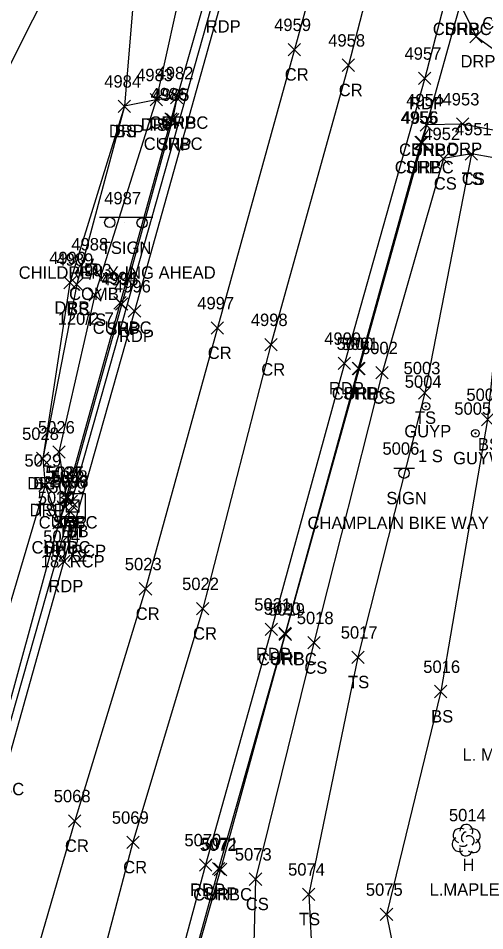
# Model space of a CAD drawing. Extents: x 1443912 to 1445411, y 621446 to 623693.
# Drawn here: x 1444769.5 to 1444844.8, y 622698.4 to 622845.6 of the extents above; entities that cross this region are included whole.
import ezdxf

# ---------------------------------------------------------------- set-up
doc = ezdxf.new("R2010")
doc.units = 0
for name, color, linetype in [('D_A', 7, 'Continuous'), ('D_C', 7, 'Continuous'), ('D_I', 7, 'Continuous'), ('D_TIC', 7, 'Continuous'), ('DCP', 7, 'Continuous'), ('DS', 7, 'Continuous'), ('L_A', 7, 'Continuous'), ('L_C', 7, 'Continuous'), ('L_I', 7, 'Continuous'), ('L_TIC', 7, 'Continuous'), ('LELB', 7, 'Continuous'), ('LTD', 7, 'Continuous'), ('P_A', 7, 'Continuous'), ('P_I', 7, 'Continuous'), ('P_TIC', 7, 'Continuous'), ('PET', 7, 'Continuous'), ('PRC', 7, 'Continuous'), ('PSP', 7, 'Continuous'), ('R_A', 7, 'Continuous'), ('R_I', 7, 'Continuous'), ('R_TIC', 7, 'Continuous'), ('RC', 7, 'Continuous'), ('RDP', 7, 'Continuous'), ('S_A', 7, 'Continuous'), ('S_C', 7, 'Continuous'), ('S_I', 7, 'Continuous'), ('SSGN', 7, 'Continuous'), ('U_A', 7, 'Continuous'), ('U_C', 7, 'Continuous'), ('U_I', 7, 'Continuous'), ('UP', 7, 'Continuous'), ('UPGW', 7, 'Continuous')]:
    doc.layers.add(name, color=color, linetype=linetype)

msp = doc.modelspace()

# ---------------------------------------------------------------- linework, layer by layer
at = {"layer": 'D_TIC'}
for points in [[(1444777.13, 622766.66), (1444779.13, 622768.66)], [(1444779.13, 622766.66), (1444777.13, 622768.66)], [(1444776.89, 622765), (1444778.89, 622767)], [(1444778.89, 622765), (1444776.89, 622767)], [(1444777.35, 622765.86), (1444779.35, 622767.86)], [(1444779.35, 622765.86), (1444777.35, 622767.86)]]:
    msp.add_lwpolyline(points, dxfattribs=at)
at = {"layer": 'DCP'}
for points in [[(1444808.17, 622873.89), (1444778.13, 622767.66)], [(1444777.89, 622766), (1444731.96, 622604.37)]]:
    msp.add_lwpolyline(points, dxfattribs=at)
at = {"layer": 'DS'}
for p, q in [((1444776.33, 622768.91), (1444780.33, 622768.91)), ((1444776.33, 622764.91), (1444776.33, 622768.91)), ((1444780.33, 622768.91), (1444780.33, 622764.91)), ((1444777.33, 622765.91), (1444777.33, 622767.91)), ((1444777.33, 622767.91), (1444779.33, 622767.91)), ((1444778.33, 622766.91), (1444778.33, 622766.91)), ((1444778.33, 622766.91), (1444778.33, 622766.91)), ((1444779.33, 622767.91), (1444779.33, 622765.91)), ((1444779.33, 622765.91), (1444777.33, 622765.91)), ((1444780.33, 622764.91), (1444776.33, 622764.91))]:
    msp.add_line(p, q, dxfattribs=at)
at = {"layer": 'L_TIC'}
for points in [[(1444790.83, 622831.44), (1444792.83, 622833.44)], [(1444792.83, 622831.44), (1444790.83, 622833.44)], [(1444785.68, 622830.4), (1444787.68, 622832.4)], [(1444787.68, 622830.4), (1444785.68, 622832.4)], [(1444841.7, 622822.71), (1444843.7, 622824.71)], [(1444843.7, 622822.71), (1444841.7, 622824.71)], [(1444841.7, 622822.71), (1444843.7, 622824.71)], [(1444843.7, 622822.71), (1444841.7, 622824.71)], [(1444837.18, 622821.94), (1444839.18, 622823.94)], [(1444839.18, 622821.94), (1444837.18, 622823.94)], [(1444777.98, 622801.67), (1444779.98, 622803.67)], [(1444779.98, 622801.67), (1444777.98, 622803.67)], [(1444780.91, 622799.96), (1444782.91, 622801.96)], [(1444782.91, 622799.96), (1444780.91, 622801.96)], [(1444827.28, 622787.41), (1444829.28, 622789.41)], [(1444829.28, 622787.41), (1444827.28, 622789.41)], [(1444834.16, 622784.16), (1444836.16, 622786.16)], [(1444836.16, 622784.16), (1444834.16, 622786.16)], [(1444844.3, 622779.86), (1444846.3, 622781.86)], [(1444846.3, 622779.86), (1444844.3, 622781.86)], [(1444775.12, 622774.61), (1444777.12, 622776.61)], [(1444777.12, 622774.61), (1444775.12, 622776.61)], [(1444772.49, 622773.57), (1444774.49, 622775.57)], [(1444774.49, 622773.57), (1444772.49, 622775.57)], [(1444772.88, 622769.26), (1444774.88, 622771.26)], [(1444774.88, 622769.26), (1444772.88, 622771.26)], [(1444776.26, 622767.28), (1444778.26, 622769.28)], [(1444778.26, 622767.28), (1444776.26, 622769.28)], [(1444816.27, 622743.85), (1444818.27, 622745.85)], [(1444818.27, 622743.85), (1444816.27, 622745.85)], [(1444823.37, 622741.51), (1444825.37, 622743.51)], [(1444825.37, 622741.51), (1444823.37, 622743.51)], [(1444836.75, 622735.98), (1444838.75, 622737.98)], [(1444838.75, 622735.98), (1444836.75, 622737.98)], [(1444806.84, 622705.71), (1444808.84, 622707.71)], [(1444808.84, 622705.71), (1444806.84, 622707.71)], [(1444815.44, 622703.28), (1444817.44, 622705.28)], [(1444817.44, 622703.28), (1444815.44, 622705.28)], [(1444827.99, 622700.03), (1444829.99, 622702.03)], [(1444829.99, 622700.03), (1444827.99, 622702.03)]]:
    msp.add_lwpolyline(points, dxfattribs=at)
at = {"layer": 'LELB'}
for points in [[(1444811.03, 622920.19), (1444805.86, 622901.27), (1444796.98, 622873.71), (1444788.55, 622853.46), (1444786.68, 622831.4), (1444778.98, 622802.67), (1444773.49, 622774.57)], [(1444816.81, 622920.88), (1444810.49, 622899.85), (1444802.1, 622872.91), (1444796.47, 622853.54), (1444791.83, 622832.44), (1444781.91, 622800.96), (1444776.12, 622775.61), (1444777.26, 622768.28)], [(1444792.95, 622883.72), (1444778.49, 622873.44), (1444776.4, 622854.4), (1444762.6, 622826.98), (1444757.09, 622807.45), (1444753.41, 622780.37), (1444747.22, 622757.91)], [(1444842.7, 622823.71), (1444838.18, 622822.94), (1444828.28, 622788.41), (1444817.27, 622744.85), (1444807.84, 622706.71), (1444806.91, 622671.56), (1444799.51, 622655.2), (1444807.31, 622617.57), (1444820.7, 622606.65), (1444828.22, 622620.73)], [(1444890.06, 622808.81), (1444861.97, 622818.47), (1444849.89, 622822.42), (1444842.7, 622823.71), (1444835.16, 622785.16), (1444824.37, 622742.51), (1444816.44, 622704.28), (1444818.25, 622669.78), (1444815.91, 622649.72), (1444822.81, 622619.36), (1444828.22, 622620.73), (1444847.1, 622600.83), (1444898.42, 622597.33), (1444911.1, 622598.15), (1444918.34, 622603.19), (1444925.63, 622624.78), (1444933.67, 622652.67)], [(1444889.09, 622803.35), (1444859.51, 622810.13), (1444848.33, 622810.8), (1444845.3, 622780.86), (1444837.75, 622736.98), (1444828.99, 622701.03), (1444836.21, 622665.57), (1444855.32, 622642.52), (1444847.1, 622600.83), (1444898.8, 622600.84), (1444910.44, 622603.25), (1444916.42, 622625.03), (1444924.69, 622654.57)], [(1444773.88, 622770.26), (1444764.75, 622739.55), (1444761.74, 622726.64), (1444754.33, 622699.97), (1444750.13, 622690.5), (1444742.96, 622660.85), (1444734.14, 622627.58), (1444728, 622607.35), (1444720.98, 622595.3), (1444711.87, 622586.94), (1444701.97, 622580.42)]]:
    msp.add_lwpolyline(points, dxfattribs=at)
at = {"layer": 'LTD'}
msp.add_line((1444841.83, 622713.04), (1444841.83, 622713.04), dxfattribs=at)
msp.add_line((1444841.83, 622713.04), (1444841.83, 622713.04), dxfattribs=at)
msp.add_arc((1444841.87, 622714.48), 1.05, 335.5272, 180.9563, dxfattribs=at)
for centre, major_axis, ratio, start_param, end_param in [((1444841.04, 622713.71), (1.21, -0.51), 0.895232, 1.570796, 4.712389), ((1444841.62, 622713.5), (-0.208, -0.792), 0.645439, 3.141593, 6.283185), ((1444842.33, 622712.88), (-0.5, 0.667), 0.989748, 3.141593, 6.283185), ((1444842.87, 622713.63), (-1.14, -0.48), 0.949671, 1.570796, 4.712389), ((1444840.74, 622712.33), (0.58, -1.04), 0.959034, 3.141593, 6.283185), ((1444841.37, 622712.29), (-0.625, -0.083), 0.423636, 0, 3.141593), ((1444842.83, 622712.21), (-1.09, 0.79), 0.841452, 1.570796, 4.712389), ((1444841.83, 622711.54), (0.26, 1.06), 0.942809, 1.570796, 4.712389)]:
    msp.add_ellipse(centre, major_axis=major_axis, ratio=ratio, start_param=start_param, end_param=end_param, dxfattribs=at)
at = {"layer": 'P_TIC'}
for points in [[(1444813.12, 622839.53), (1444815.12, 622841.53)], [(1444815.12, 622839.53), (1444813.12, 622841.53)], [(1444821.84, 622837.02), (1444823.84, 622839.02)], [(1444823.84, 622837.02), (1444821.84, 622839.02)], [(1444834.15, 622834.9), (1444836.15, 622836.9)], [(1444836.15, 622834.9), (1444834.15, 622836.9)], [(1444794.13, 622831.76), (1444796.13, 622833.76)], [(1444796.13, 622831.76), (1444794.13, 622833.76)], [(1444793.46, 622828.25), (1444795.46, 622830.25)], [(1444795.46, 622828.25), (1444793.46, 622830.25)], [(1444834.43, 622827.39), (1444836.43, 622829.39)], [(1444836.43, 622827.39), (1444834.43, 622829.39)], [(1444833.54, 622824.57), (1444835.54, 622826.57)], [(1444835.54, 622824.57), (1444833.54, 622826.57)], [(1444785.25, 622798.5), (1444787.25, 622800.5)], [(1444787.25, 622798.5), (1444785.25, 622800.5)], [(1444787.31, 622797.36), (1444789.31, 622799.36)], [(1444789.31, 622797.36), (1444787.31, 622799.36)], [(1444800.7, 622794.63), (1444802.7, 622796.63)], [(1444802.7, 622794.63), (1444800.7, 622796.63)], [(1444809.34, 622791.94), (1444811.34, 622793.94)], [(1444811.34, 622791.94), (1444809.34, 622793.94)], [(1444821.19, 622788.91), (1444823.19, 622790.91)], [(1444823.19, 622788.91), (1444821.19, 622790.91)], [(1444823.43, 622788.09), (1444825.43, 622790.09)], [(1444825.43, 622788.09), (1444823.43, 622790.09)], [(1444776.57, 622767.3), (1444778.57, 622769.3)], [(1444778.57, 622767.3), (1444776.57, 622769.3)], [(1444775.11, 622763.24), (1444777.11, 622765.24)], [(1444777.11, 622763.24), (1444775.11, 622765.24)], [(1444775.91, 622756.99), (1444777.91, 622758.99)], [(1444777.91, 622756.99), (1444775.91, 622758.99)], [(1444789.08, 622752.54), (1444791.08, 622754.54)], [(1444791.08, 622752.54), (1444789.08, 622754.54)], [(1444798.32, 622749.35), (1444800.32, 622751.35)], [(1444800.32, 622749.35), (1444798.32, 622751.35)], [(1444809.41, 622746.03), (1444811.41, 622748.03)], [(1444811.41, 622746.03), (1444809.41, 622748.03)], [(1444811.61, 622745.36), (1444813.61, 622747.36)], [(1444813.61, 622745.36), (1444811.61, 622747.36)], [(1444777.65, 622715.11), (1444779.65, 622717.11)], [(1444779.65, 622715.11), (1444777.65, 622717.11)], [(1444787.05, 622711.65), (1444789.05, 622713.65)], [(1444789.05, 622711.65), (1444787.05, 622713.65)], [(1444798.78, 622708.01), (1444800.78, 622710.01)], [(1444800.78, 622708.01), (1444798.78, 622710.01)], [(1444800.88, 622707.4), (1444802.88, 622709.4)], [(1444802.88, 622707.4), (1444800.88, 622709.4)]]:
    msp.add_lwpolyline(points, dxfattribs=at)
at = {"layer": 'PET'}
for points in [[(1444834.61, 622954.83), (1444817.28, 622898.33), (1444802.32, 622848.28), (1444788.31, 622798.36), (1444776.91, 622757.99), (1444766.34, 622720.55), (1444757.14, 622686.8), (1444749.1, 622658.64), (1444739.41, 622623.83), (1444737.32, 622616.48)], [(1444863.33, 622947.05), (1444849.43, 622890.74), (1444835.15, 622835.9), (1444822.19, 622789.91), (1444810.41, 622747.03), (1444799.78, 622709.01), (1444791.19, 622677.27), (1444783.21, 622648.5), (1444773.16, 622611.58)]]:
    msp.add_lwpolyline(points, dxfattribs=at)
at = {"layer": 'PRC'}
for points in [[(1444864.1, 623005.34), (1444851.39, 622950.16), (1444837.25, 622893.61), (1444822.84, 622838.02), (1444810.34, 622792.94), (1444799.32, 622750.35), (1444788.05, 622712.65), (1444779.51, 622680.27), (1444771.55, 622651.63), (1444762.01, 622615.65), (1444752.75, 622584.12), (1444739.92, 622538.84), (1444733.6, 622516.91), (1444722.13, 622475.76), (1444713.59, 622446.41), (1444702.09, 622404.55), (1444689.87, 622361.08), (1444676.17, 622311.92), (1444657.59, 622249.98), (1444643.66, 622204.01), (1444635.38, 622177.66), (1444620.59, 622126.88), (1444604.97, 622075.74)], [(1444846.73, 622950.74), (1444829.37, 622896.11), (1444814.12, 622840.53), (1444801.7, 622795.63), (1444790.08, 622753.54), (1444778.65, 622716.11), (1444769.12, 622683.18), (1444760.94, 622654.81), (1444750.77, 622619.03), (1444741.67, 622586.01), (1444729.73, 622541.23), (1444723.42, 622520.39), (1444711.77, 622478.97), (1444703.65, 622449.63), (1444691.66, 622407.43), (1444679.51, 622365.85), (1444664.93, 622313.64), (1444649.43, 622253.98), (1444637.04, 622206.21), (1444631.31, 622178.74), (1444618.32, 622127.38), (1444604.97, 622075.74)]]:
    msp.add_lwpolyline(points, dxfattribs=at)
at = {"layer": 'PSP'}
for points in [[(1444830.72, 622958.68), (1444824.08, 622936.54), (1444819.67, 622919.33), (1444819.08, 622916.76), (1444813.82, 622898.85), (1444807.44, 622876.3), (1444806.37, 622872.29), (1444795.13, 622832.76), (1444794.46, 622829.25), (1444786.25, 622799.5), (1444777.57, 622768.3), (1444776.11, 622764.24), (1444765.41, 622725.24), (1444764.56, 622721.65), (1444754.92, 622687.33)], [(1444868.68, 622947.27), (1444864.21, 622931.67), (1444863.42, 622928.8), (1444852.73, 622889.78), (1444841.93, 622851.99), (1444840.88, 622847.88), (1444835.43, 622828.39), (1444834.54, 622825.57), (1444824.43, 622789.09), (1444812.61, 622746.36), (1444801.88, 622708.4), (1444793.15, 622676.92), (1444788.83, 622661.85), (1444786.44, 622649.3), (1444783.88, 622637.22), (1444773.11, 622588.76)]]:
    msp.add_lwpolyline(points, dxfattribs=at)
at = {"layer": 'R_TIC'}
for points in [[(1444842.44, 622841.65), (1444844.44, 622843.65)], [(1444844.44, 622841.65), (1444842.44, 622843.65)], [(1444790.83, 622831.44), (1444792.83, 622833.44)], [(1444792.83, 622831.44), (1444790.83, 622833.44)], [(1444794.13, 622831.76), (1444796.13, 622833.76)], [(1444796.13, 622831.76), (1444794.13, 622833.76)], [(1444794.13, 622831.76), (1444796.13, 622833.76)], [(1444796.13, 622831.76), (1444794.13, 622833.76)], [(1444785.68, 622830.4), (1444787.68, 622832.4)], [(1444787.68, 622830.4), (1444785.68, 622832.4)], [(1444793.21, 622828.35), (1444795.21, 622830.35)], [(1444795.21, 622828.35), (1444793.21, 622830.35)], [(1444834.43, 622827.39), (1444836.43, 622829.39)], [(1444836.43, 622827.39), (1444834.43, 622829.39)], [(1444834.43, 622827.39), (1444836.43, 622829.39)], [(1444836.43, 622827.39), (1444834.43, 622829.39)], [(1444840.29, 622827.53), (1444842.29, 622829.53)], [(1444842.29, 622827.53), (1444840.29, 622829.53)], [(1444833.74, 622824.57), (1444835.74, 622826.57)], [(1444835.74, 622824.57), (1444833.74, 622826.57)], [(1444776.89, 622801.92), (1444778.89, 622803.92)], [(1444778.89, 622801.92), (1444776.89, 622803.92)], [(1444784.97, 622798.68), (1444786.97, 622800.68)], [(1444786.97, 622798.68), (1444784.97, 622800.68)], [(1444823.56, 622788.07), (1444825.56, 622790.07)], [(1444825.56, 622788.07), (1444823.56, 622790.07)], [(1444772.49, 622773.57), (1444774.49, 622775.57)], [(1444774.49, 622773.57), (1444772.49, 622775.57)], [(1444772.88, 622769.26), (1444774.88, 622771.26)], [(1444774.88, 622769.26), (1444772.88, 622771.26)], [(1444776.26, 622767.28), (1444778.26, 622769.28)], [(1444778.26, 622767.28), (1444776.26, 622769.28)], [(1444775.11, 622763.24), (1444777.11, 622765.24)], [(1444777.11, 622763.24), (1444775.11, 622765.24)], [(1444775.11, 622763.24), (1444777.11, 622765.24)], [(1444777.11, 622763.24), (1444775.11, 622765.24)], [(1444811.65, 622745.22), (1444813.65, 622747.22)], [(1444813.65, 622745.22), (1444811.65, 622747.22)], [(1444801.19, 622707.27), (1444803.19, 622709.27)], [(1444803.19, 622707.27), (1444801.19, 622709.27)]]:
    msp.add_lwpolyline(points, dxfattribs=at)
at = {"layer": 'RC'}
for points in [[(1444795.13, 622832.76), (1444794.21, 622829.35), (1444785.97, 622799.68), (1444777.26, 622768.28), (1444776.11, 622764.24)], [(1444835.43, 622828.39), (1444834.74, 622825.57), (1444824.56, 622789.07), (1444812.65, 622746.22), (1444802.19, 622708.27), (1444793.28, 622676.84), (1444789.04, 622661.79), (1444786.8, 622649.09), (1444787.6, 622638.38), (1444789.9, 622630.26), (1444794.92, 622619.88), (1444800, 622613.35), (1444805.15, 622608.7), (1444814.5, 622602.52), (1444825.46, 622598.68), (1444828.32, 622597.96)]]:
    msp.add_lwpolyline(points, dxfattribs=at)
at = {"layer": 'RDP'}
for points in [[(1444840.88, 622847.88), (1444843.44, 622842.65), (1444848.62, 622838.88), (1444853.85, 622836.81), (1444851.42, 622826.53), (1444841.29, 622828.53), (1444835.43, 622828.39)], [(1444795.13, 622832.76), (1444791.83, 622832.44), (1444786.68, 622831.4), (1444777.89, 622802.92), (1444773.49, 622774.57), (1444773.88, 622770.26), (1444776.11, 622764.24)]]:
    msp.add_lwpolyline(points, dxfattribs=at)
at = {"layer": 'SSGN'}
for p, q in [((1444782.66, 622813.49), (1444791.26, 622813.49)), ((1444786.68, 622812.58), (1444786.68, 622812.58)), ((1444830.17, 622773.03), (1444833.51, 622773.03)), ((1444831.82, 622772.2), (1444831.82, 622772.2))]:
    msp.add_line(p, q, dxfattribs=at)
for centre in [(1444784.32, 622812.65), (1444789.54, 622812.58), (1444831.82, 622772.2)]:
    msp.add_circle(centre, 0.833, dxfattribs=at)
at = {"layer": 'UP'}
for p, q in [((1444781.62, 622806.8), (1444781.37, 622805.97)), ((1444780.54, 622804.3), (1444780.54, 622805.97)), ((1444780.54, 622805.97), (1444782.2, 622805.97)), ((1444781.37, 622805.14), (1444781.37, 622805.14)), ((1444782.2, 622805.97), (1444782.2, 622804.3)), ((1444782.2, 622804.3), (1444780.54, 622804.3)), ((1444781.12, 622803.47), (1444781.37, 622804.3))]:
    msp.add_line(p, q, dxfattribs=at)
msp.add_circle((1444781.37, 622805.14), 0.833, dxfattribs=at)
at = {"layer": 'UPGW'}
for centre, radius in [((1444835.35, 622782.98), 0.625), ((1444835.35, 622782.98), 0.0833), ((1444843.34, 622778.63), 0.625), ((1444843.34, 622778.63), 0.0833)]:
    msp.add_circle(centre, radius, dxfattribs=at)

# ---------------------------------------------------------------- texts
at = {"layer": 'D_A'}
for s, p in [('DIB', (1444776.45, 622761.86)), ('DI', (1444777.39, 622761.91)), ('P', (1444777.51, 622762.66)), ('P', (1444777.27, 622761))]:
    msp.add_text(s, height=2, dxfattribs=at).set_placement(p)
at = {"layer": 'D_C'}
for s, p in [('18" RCP', (1444773.41, 622758.66)), ('2X2', (1444775.91, 622757.91)), ('18" RCP', (1444773.17, 622757))]:
    msp.add_text(s, height=2, dxfattribs=at).set_placement(p)
at = {"layer": 'D_I'}
for s, p in [('5098', (1444774.79, 622770.66)), ('5096', (1444774.94, 622769.91)), ('5097', (1444775.01, 622769.86)), ('5099', (1444774.54, 622769))]:
    msp.add_text(s, height=2, dxfattribs=at).set_placement(p)
at = {"layer": 'L_A'}
for s, p in [('CS', (1444844.44, 622843.77)), ('TS', (1444790.24, 622827.44)), ('BS', (1444785.12, 622826.4)), ('CS', (1444836.62, 622817.94)), ('TS', (1444841.11, 622818.71)), ('CS', (1444841.14, 622818.71)), ('BS', (1444777.42, 622797.67)), ('TS', (1444780.32, 622795.96)), ('CS', (1444826.73, 622783.41)), ('TS', (1444833.57, 622780.16)), ('BS', (1444843.74, 622775.86)), ('TS', (1444774.53, 622770.61)), ('BS', (1444771.94, 622769.57)), ('TS', (1444772.29, 622765.26)), ('TS', (1444775.67, 622763.28)), ('CS', (1444815.72, 622739.85)), ('TS', (1444822.78, 622737.51)), ('BS', (1444836.19, 622731.98)), ('H', (1444841.26, 622708.04)), ('CS', (1444806.28, 622701.71)), ('TS', (1444814.85, 622699.28))]:
    msp.add_text(s, height=2, dxfattribs=at).set_placement(p)
at = {"layer": 'L_C'}
for s, p in [('L. MAPLE', (1444841.25, 622725.8)), ('L.MAPLE', (1444835.94, 622704.04))]:
    msp.add_text(s, height=2, dxfattribs=at).set_placement(p)
at = {"layer": 'L_I'}
for s, p in [('4983', (1444788.57, 622835.44)), ('4984', (1444783.42, 622834.4)), ('4951', (1444840.01, 622826.71)), ('4951', (1444840.01, 622826.71)), ('4952', (1444834.92, 622825.94)), ('4989', (1444775.71, 622805.67)), ('4993', (1444778.65, 622803.96)), ('5002', (1444824.87, 622791.41)), ('5003', (1444831.74, 622788.16)), ('5007', (1444841.88, 622783.86)), ('5026', (1444772.72, 622778.61)), ('5028', (1444770.16, 622777.57)), ('5029', (1444770.54, 622773.26)), ('5027', (1444773.92, 622771.28)), ('5018', (1444814.5, 622747.85)), ('5017', (1444821.6, 622745.51)), ('5016', (1444834.92, 622739.98)), ('5014', (1444839.06, 622716.04)), ('5073', (1444804.5, 622709.71)), ('5074', (1444813.1, 622707.28)), ('5075', (1444825.65, 622704.03))]:
    msp.add_text(s, height=2, dxfattribs=at).set_placement(p)
at = {"layer": 'P_A'}
for s, p in [('RDP', (1444799.8, 622843.28)), ('SHP', (1444838.42, 622842.88)), ('CR', (1444812.56, 622835.53)), ('CR', (1444821.28, 622833.02)), ('RDP', (1444832.64, 622830.9)), ('SHP', (1444792.66, 622827.76)), ('SHP', (1444792, 622824.25)), ('SHP', (1444832.97, 622823.39)), ('SHP', (1444832.08, 622820.57)), ('SHP', (1444783.78, 622794.5)), ('RDP', (1444785.8, 622793.36)), ('CR', (1444800.13, 622790.63)), ('CR', (1444808.77, 622787.94)), ('RDP', (1444819.68, 622784.91)), ('SHP', (1444821.97, 622784.09)), ('SHP', (1444775.11, 622763.3)), ('SHP', (1444773.65, 622759.24)), ('RDP', (1444774.4, 622752.99)), ('CR', (1444788.51, 622748.54)), ('CR', (1444797.76, 622745.35)), ('RDP', (1444807.9, 622742.03)), ('SHP', (1444810.14, 622741.36)), ('CR', (1444777.08, 622711.11)), ('CR', (1444786.48, 622707.65)), ('RDP', (1444797.27, 622704.01)), ('SHP', (1444799.42, 622703.4))]:
    msp.add_text(s, height=2, dxfattribs=at).set_placement(p)
at = {"layer": 'P_I'}
for s, p in [('4959', (1444810.85, 622843.53)), ('4958', (1444819.58, 622841.02)), ('4957', (1444831.89, 622838.9)), ('4982', (1444791.87, 622835.76)), ('4985', (1444791.21, 622832.25)), ('4954', (1444832.17, 622831.39)), ('4955', (1444831.28, 622828.57)), ('4995', (1444782.99, 622802.5)), ('4996', (1444785, 622801.36)), ('4997', (1444798.44, 622798.63)), ('4998', (1444807.08, 622795.94)), ('4999', (1444818.93, 622792.91)), ('5000', (1444820.93, 622792.09)), ('5025', (1444774.24, 622771.3)), ('5030', (1444772.69, 622767.24)), ('5024', (1444773.57, 622760.99)), ('5023', (1444786.74, 622756.54)), ('5022', (1444795.99, 622753.35)), ('5021', (1444807.64, 622750.03)), ('5020', (1444809.18, 622749.36)), ('5068', (1444775.27, 622719.11)), ('5069', (1444784.65, 622715.65)), ('5070', (1444796.36, 622712.01)), ('5071', (1444799.11, 622711.4))]:
    msp.add_text(s, height=2, dxfattribs=at).set_placement(p)
at = {"layer": 'R_A'}
for s, p in [('CURBC', (1444836.46, 622842.88)), ('DRP', (1444838.37, 622842.88)), ('DRP', (1444840.93, 622837.65)), ('DRP', (1444789.32, 622827.44)), ('CURBC', (1444790.71, 622827.76)), ('DRP', (1444792.62, 622827.76)), ('DRP', (1444784.17, 622826.4)), ('CURBC', (1444789.79, 622824.35)), ('CURBC', (1444831.01, 622823.39)), ('DRP', (1444832.92, 622823.39)), ('DRP', (1444838.78, 622823.53)), ('CURBC', (1444830.32, 622820.57)), ('DRP', (1444775.38, 622797.92)), ('CURBC', (1444781.56, 622794.68)), ('CURBC', (1444820.15, 622784.07)), ('DRP', (1444770.98, 622769.57)), ('DRP', (1444771.37, 622765.26)), ('CURBC', (1444772.84, 622763.28)), ('CURBC', (1444771.69, 622759.24)), ('DRP', (1444773.6, 622759.24)), ('CURBC', (1444808.23, 622741.22)), ('CURBC', (1444760.99, 622720.24)), ('CURBC', (1444797.77, 622703.27))]:
    msp.add_text(s, height=2, dxfattribs=at).set_placement(p)
at = {"layer": 'R_I'}
for s, p in [('4983', (1444788.57, 622835.44)), ('4982', (1444791.87, 622835.76)), ('4982', (1444791.87, 622835.76)), ('4984', (1444783.42, 622834.4)), ('4986', (1444790.89, 622832.35)), ('4954', (1444832.17, 622831.39)), ('4954', (1444832.17, 622831.39)), ('4953', (1444838.03, 622831.53)), ('4956', (1444831.42, 622828.57)), ('4990', (1444774.54, 622805.92)), ('4994', (1444782.71, 622802.68)), ('5001', (1444821.71, 622792.07)), ('5028', (1444770.16, 622777.57)), ('5029', (1444770.54, 622773.26)), ('5027', (1444773.92, 622771.28)), ('5030', (1444772.69, 622767.24)), ('5030', (1444772.69, 622767.24)), ('5019', (1444809.87, 622749.22)), ('5072', (1444798.85, 622711.27))]:
    msp.add_text(s, height=2, dxfattribs=at).set_placement(p)
at = {"layer": 'S_A'}
for s, p in [('TSIGN', (1444782.86, 622807.57)), ('SIGN', (1444828.96, 622767.18))]:
    msp.add_text(s, height=2, dxfattribs=at).set_placement(p)
at = {"layer": 'S_C'}
for s, p in [('CHILDREN X-ING AHEAD', (1444769.61, 622803.57)), ('CHAMPLAIN BIKE WAY', (1444816.23, 622763.18))]:
    msp.add_text(s, height=2, dxfattribs=at).set_placement(p)
at = {"layer": 'S_I'}
for s, p in [('4987', (1444783.42, 622815.57)), ('5006', (1444828.33, 622775.18))]:
    msp.add_text(s, height=2, dxfattribs=at).set_placement(p)
at = {"layer": 'U_A'}
for s, p in [('COMB', (1444777.75, 622800.14)), ('GUYP', (1444831.86, 622777.98)), ('GUYW', (1444839.74, 622773.63))]:
    msp.add_text(s, height=2, dxfattribs=at).set_placement(p)
at = {"layer": 'U_C'}
for s, p in [('120/2-7', (1444775.9, 622796.14)), ('1 S', (1444834.07, 622773.98))]:
    msp.add_text(s, height=2, dxfattribs=at).set_placement(p)
at = {"layer": 'U_I'}
for s, p in [('4988', (1444778.11, 622808.14)), ('5004', (1444831.93, 622785.98)), ('5005', (1444839.93, 622781.63))]:
    msp.add_text(s, height=2, dxfattribs=at).set_placement(p)

doc.saveas('drawing.dxf')
